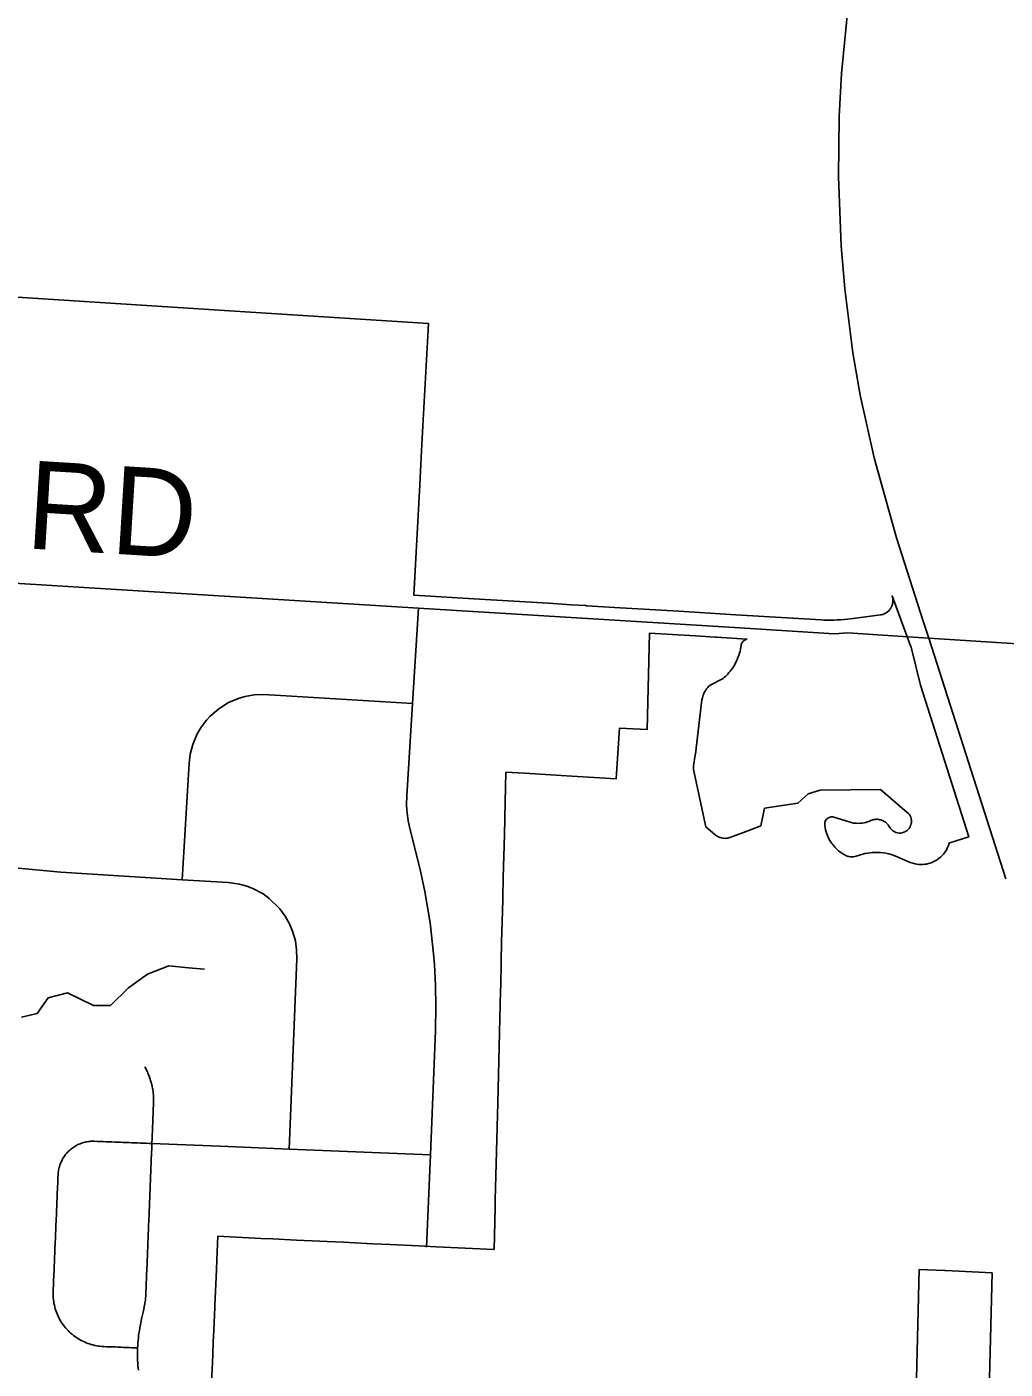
# Model space of a CAD drawing. Extents: x 114604 to 551442, y 316898 to 567001.
# Drawn here: x 175902 to 179238, y 463739 to 468313 of the extents above; entities that cross this region are included whole.
import ezdxf

# ---------------------------------------------------------------- set-up
doc = ezdxf.new("R2010")
doc.units = 0
for name, color, linetype in [('GE_P_Alignment_1000_Cardinal_Points', 7, 'Continuous'), ('GE_P_Alignment_100_Stations', 7, 'Continuous'), ('GE_P_Alignment_500_Bearings', 7, 'Continuous'), ('PM_P_Cells', 7, 'Continuous'), ('PM_P_Crosswalk', 7, 'Continuous')]:
    doc.layers.add(name, color=color, linetype=linetype)

msp = doc.modelspace()

# ---------------------------------------------------------------- linework, layer by layer
at = {"layer": 'GE_P_Alignment_1000_Cardinal_Points'}
for points in [[(173646.4, 466554.1), (173989.4, 466534.2), (174897, 466477.2), (175876.9, 466416.2), (177237.4, 466331.4), (178315.2, 466265.7), (178655.4, 466244.4), (178701.9, 466247.6), (178871.6, 466236.5)], [(177237.4, 466331.4), (177217.2, 466006.9), (177197.7, 465692.9), (177197.2, 465662.4), (177198.1, 465644.1), (177200, 465625.9), (177202.9, 465607.8), (177207.4, 465586.6), (177244.6, 465436.1), (177259.5, 465366.1), (177277.2, 465260.2), (177289.3, 465153.6), (177292.2, 465117.9), (177295.9, 465046.5), (177297.1, 464975), (177295.5, 464891.9), (177278.3, 464469.1), (177265.5, 464154.2)], [(178871.6, 466236.5), (178977.7, 466229.5), (179884.8, 466171.3), (180261.7, 466147.3)], [(176431.4, 465406.3), (176455.5, 465803.4), (176459.3, 465834), (176468.1, 465867.8), (176483.4, 465903.9), (176496.7, 465926.4), (176515.1, 465950.8), (176526.9, 465963.6), (176556.6, 465989.3), (176589.8, 466010.1), (176625.9, 466025.4), (176646.9, 466031.4), (176677, 466036.6), (176707.5, 466038.2), (176767.7, 466034.6), (177217.2, 466006.9)], [(175872.6, 465446.1), (176017.8, 465432.1), (176431.4, 465406.3), (176588.2, 465396.8), (176627.3, 465391.3), (176652.5, 465384.3), (176672.8, 465376.4), (176707.5, 465358), (176728.7, 465342.8), (176765.3, 465307), (176783.3, 465282.4), (176798.2, 465255.7), (176808.3, 465231.6), (176817.8, 465198), (176822.1, 465167.8), (176822.8, 465137.1), (176796.4, 464488.7)], [(176282.7, 463734.9), (176281.8, 463743.4), (176281.1, 463751.8), (176280.5, 463760.2), (176280, 463768.7), (176279.7, 463777.2), (176279.6, 463785.7), (176279.5, 463794.1), (176279.7, 463802.6), (176280, 463811.1), (176280.3, 463819.6), (176280.9, 463828), (176281.6, 463836.5), (176282.5, 463844.9), (176283.5, 463853.4), (176284.6, 463861.8), (176285.9, 463870.2), (176287.3, 463878.6), (176288.9, 463886.9), (176290.5, 463895.3), (176292.6, 463904.8), (176294.6, 463914.3), (176296.7, 463923.8), (176298.7, 463933.4), (176300.7, 463942.9), (176302.8, 463952.4), (176303.6, 463956.6), (176304.4, 463960.8), (176305.1, 463965), (176305.7, 463969.2), (176306.3, 463973.4), (176306.8, 463977.6), (176307.2, 463981.8), (176307.6, 463986.1), (176307.8, 463990.3), (176308.1, 463994.5), (176308.4, 464004.4), (176308.8, 464014.3), (176309.2, 464024.1), (176309.6, 464034), (176310, 464043.9), (176310.4, 464053.7), (176310.8, 464063.6), (176311.2, 464073.5), (176311.6, 464083.3), (176312, 464093.2), (176312.4, 464103.1), (176312.8, 464112.9), (176313.2, 464122.8), (176313.6, 464132.7), (176314, 464142.5), (176314.4, 464152.4), (176314.8, 464162.3), (176315.2, 464172.2), (176315.6, 464182), (176316, 464191.9), (176316.4, 464201.7), (176316.8, 464211.6), (176317.2, 464221.5), (176317.6, 464231.3), (176318, 464241.2), (176318.4, 464251.1), (176318.8, 464260.9), (176319.2, 464270.8), (176319.6, 464280.7), (176320, 464290.5), (176320.4, 464300.4), (176320.8, 464310.3), (176321.2, 464320.1), (176321.6, 464330), (176322, 464339.9), (176322.4, 464349.7), (176322.8, 464359.6), (176323.1, 464369.5), (176323.6, 464379.3), (176323.9, 464389.2), (176324.3, 464399.1), (176324.8, 464408.9), (176325.1, 464418.8), (176325.5, 464428.7), (176326, 464438.5), (176326.3, 464448.4), (176326.7, 464458.3), (176327.1, 464468.1), (176327.5, 464478), (176327.9, 464487.9), (176328.3, 464497.7), (176328.7, 464507.6), (176329.5, 464527.5), (176329.9, 464537.5), (176330.3, 464547.4), (176330.7, 464557.4), (176331.1, 464567.3), (176331.5, 464577.3), (176331.9, 464587.2), (176332.3, 464597.2), (176332.7, 464607.1), (176333.1, 464617.1), (176333.5, 464627), (176333.9, 464637), (176334.3, 464646.9), (176334.5, 464650.8), (176334.5, 464654.6), (176334.5, 464658.5), (176334.4, 464662.3), (176334.3, 464666.1), (176334.1, 464670), (176333.8, 464673.8), (176333.5, 464677.6), (176333.1, 464681.5), (176332.6, 464685.3), (176332.1, 464689.1), (176331.5, 464692.9), (176330.8, 464696.7), (176330.1, 464700.4), (176329.3, 464704.2), (176328.4, 464708), (176327.5, 464711.7), (176326.6, 464715.4), (176325.5, 464719.1), (176324.4, 464722.8), (176323.2, 464726.4), (176322, 464730.1), (176320.7, 464733.7), (176319.3, 464737.3), (176317.9, 464740.9), (176316.4, 464744.4), (176314.9, 464747.9), (176313.3, 464751.4), (176311.6, 464754.9), (176309.9, 464758.3), (176308.1, 464761.7), (176306.3, 464765.1), (176304.4, 464768.5)], [(176280, 463811.1), (176270.3, 463811.5), (176260.7, 463811.9), (176251.1, 463812.3), (176241.5, 463812.7), (176231.8, 463813.1), (176222.2, 463813.5), (176212.6, 463813.9), (176203, 463814.3), (176193.4, 463814.7), (176183.8, 463815.1), (176174.1, 463815.4), (176164.5, 463815.9), (176158.3, 463816.2), (176152.1, 463816.8), (176145.9, 463817.6), (176139.8, 463818.6), (176133.7, 463819.8), (176127.6, 463821.2), (176121.7, 463822.8), (176115.7, 463824.7), (176109.9, 463826.7), (176104, 463829), (176098.3, 463831.4), (176092.7, 463834), (176087.1, 463836.9), (176081.7, 463839.9), (176076.4, 463843.1), (176071.2, 463846.5), (176066.1, 463850), (176061.1, 463853.8), (176056.3, 463857.7), (176051.6, 463861.8), (176047, 463866), (176042.6, 463870.4), (176038.3, 463874.9), (176034.3, 463879.6), (176030.3, 463884.4), (176026.6, 463889.4), (176023, 463894.5), (176019.6, 463899.7), (176016.3, 463905), (176013.3, 463910.4), (176010.5, 463915.9), (176007.8, 463921.6), (176005.4, 463927.3), (176003.1, 463933), (176001, 463938.9), (175999.2, 463944.9), (175997.5, 463950.9), (175996, 463956.9), (175994.8, 463963), (175993.8, 463969.1), (175993, 463975.3), (175992.4, 463981.5), (175992, 463987.7), (175991.8, 463993.9), (175991.9, 464000.1), (175992.4, 464013.2), (175992.8, 464023.1), (175993.2, 464033), (175993.7, 464043), (175994, 464052.9), (175994.5, 464062.8), (175994.9, 464072.8), (175995.3, 464082.7), (175995.7, 464092.6), (175996.1, 464102.6), (175996.6, 464112.5), (175997, 464122.4), (175997.4, 464132.4), (175997.8, 464142.3), (175998.2, 464152.3), (175998.6, 464162.2), (175999.1, 464172.1), (175999.5, 464182.1), (175999.9, 464192), (176000.3, 464201.9), (176000.7, 464211.9), (176001.1, 464221.8), (176001.5, 464231.7), (176002, 464241.7), (176002.4, 464251.6), (176002.8, 464261.5), (176003.2, 464271.5), (176003.7, 464281.4), (176004, 464291.4), (176004.5, 464301.3), (176004.9, 464311.2), (176005.3, 464321.2), (176005.7, 464331.1), (176006.1, 464341), (176006.6, 464351), (176007, 464360.9), (176007.4, 464370.8), (176007.8, 464380.8), (176008.2, 464390.7), (176008.6, 464400.6), (176008.9, 464404.8), (176009.3, 464409), (176009.8, 464413.1), (176010.5, 464417.3), (176011.3, 464421.3), (176012.3, 464425.4), (176013.4, 464429.5), (176014.7, 464433.4), (176016, 464437.4), (176017.6, 464441.3), (176019.2, 464445.2), (176021, 464448.9), (176023, 464452.6), (176025, 464456.3), (176027.2, 464459.8), (176029.5, 464463.3), (176031.9, 464466.8), (176034.4, 464470.1), (176037.1, 464473.3), (176039.9, 464476.5), (176042.7, 464479.5), (176045.7, 464482.5), (176048.8, 464485.3), (176052, 464488), (176055.2, 464490.6), (176058.6, 464493.1), (176062.1, 464495.5), (176065.6, 464497.8), (176069.2, 464499.9), (176072.8, 464501.9), (176076.6, 464503.8), (176080.4, 464505.5), (176084.2, 464507.1), (176088.2, 464508.6), (176092.1, 464510), (176096.1, 464511.2), (176100.2, 464512.2), (176104.2, 464513.1), (176108.4, 464513.9), (176112.5, 464514.5), (176116.7, 464515), (176120.8, 464515.3), (176125, 464515.5), (176129.2, 464515.6), (176133.4, 464515.5), (176143.1, 464515.1), (176152.9, 464514.7), (176162.7, 464514.3), (176172.5, 464513.9), (176182.2, 464513.5), (176192, 464513.1), (176201.8, 464512.7), (176211.5, 464512.4), (176221.3, 464511.9), (176231.1, 464511.5), (176240.8, 464511.2), (176250.6, 464510.8), (176260.3, 464510.4), (176270.1, 464510), (176279.9, 464509.6), (176289.7, 464509.2), (176299.4, 464508.8), (176309.2, 464508.4), (176319, 464508), (176328.7, 464507.6), (176588.6, 464497.1)], [(176588.6, 464497.1), (176796.4, 464488.7), (177278.3, 464469.1)]]:
    msp.add_lwpolyline(points, dxfattribs=at)
at = {"layer": 'GE_P_Alignment_100_Stations'}
for points in [[(176530.8, 463670.6), (176534.8, 463762), (176535.9, 463788.4), (176537.8, 463831.7), (176539.5, 463870.4), (176543, 463950.3), (176543.2, 463955.5), (176548.5, 464077.7), (176549.9, 464109.9), (176553.4, 464191.4), (176700.2, 464184.4), (176741.2, 464182.5), (176821.7, 464178.6), (176901.6, 464174.8), (176926, 464173.7), (176981.5, 464171), (177061.4, 464167.2), (177081.9, 464166.2), (177141.3, 464163.4), (177237.9, 464158.8), (177297.9, 464156), (177495.3, 464146.6), (177498.9, 464288.4), (177499.5, 464315.8), (177501.6, 464398.1), (177507.9, 464646), (177514, 464886.4), (177517.6, 465029.2), (177518, 465045.7), (177519.9, 465123), (177520.1, 465128.9), (177521.2, 465193.5), (177523, 465263.2), (177524.8, 465338.2), (177525.1, 465347.3), (177526.7, 465413.2), (177528.6, 465488.2), (177529.4, 465520.6), (177531.6, 465609.8), (177531.8, 465617), (177533.1, 465670.5), (177535.6, 465773), (177599.4, 465769.1), (177760.9, 465759.4), (177836.7, 465754.8), (177911.9, 465750.5), (177923.2, 465923.5), (178017.4, 465918.3), (178025.4, 466247.2), (178182.3, 466237.6), (178249.8, 466233.3), (178254.1, 466233), (178357.5, 466226.7), (178357.4, 466225.8), (178356.1, 466225.5), (178353.6, 466224.7), (178351.2, 466223.7), (178349, 466222.4), (178346.8, 466220.8), (178344.9, 466219.1), (178343.1, 466217.2), (178341.6, 466215.1), (178340.3, 466212.8), (178339.2, 466210.4), (178338.1, 466206.7), (178336.4, 466196.3), (178336, 466194.4), (178335.1, 466190.2), (178334, 466185.3), (178332, 466178.7), (178331.1, 466175), (178330.1, 466172), (178328, 466166.1), (178325.8, 466160.2), (178321.9, 466151.6), (178319.1, 466146), (178316.2, 466140.5), (178311.3, 466132.4), (178306.1, 466124.5), (178300.4, 466117), (178296.4, 466112.2), (178292.3, 466107.4), (178285.7, 466100.7), (178281.2, 466096.3), (178276.5, 466092.1), (178232, 466069.8), (178227.8, 466065.9), (178223.8, 466061.8), (178220.2, 466057.3), (178216.9, 466052.7), (178215.2, 466050), (178213.6, 466047.3), (178212.1, 466044.5), (178210.8, 466041.6), (178210.2, 466040.4), (178208, 466034.9), (178206.7, 466030.8), (178205.6, 466026.7), (178204.3, 466019.6), (178185, 465854.5), (178183.3, 465842.9), (178181.5, 465831.4), (178175.3, 465795.1), (178175.1, 465782.3), (178218, 465586.6), (178232.6, 465574.2), (178249.8, 465559.5), (178253.9, 465556.4), (178256.9, 465554.5), (178259.9, 465552.8), (178263.1, 465551.4), (178266.4, 465550.2), (178269.7, 465549.2), (178274.9, 465548.2), (178278.3, 465547.8), (178283.6, 465547.6), (178287.1, 465547.9), (178292.2, 465548.6), (178295.6, 465549.5), (178299.8, 465550.8), (178345.5, 465568), (178404.6, 465590.2), (178417.9, 465650.3), (178531.6, 465667), (178566.9, 465699.6), (178607.2, 465711.9), (178813.2, 465713.9), (178904.5, 465636.1), (178908, 465632.7), (178911.5, 465628.4), (178913, 465626), (178914.9, 465622.3), (178916, 465619.7), (178917.3, 465615.7), (178918.1, 465611.6), (178918.4, 465608.9), (178918.6, 465606.1), (178918.4, 465601.9), (178917.8, 465597.7), (178916.7, 465593.7), (178915.8, 465591), (178914.1, 465587.2), (178912, 465583.6), (178910.3, 465581.3), (178907.6, 465578.2), (178905.7, 465576.2), (178902.4, 465573.5), (178897.7, 465570.5), (178892.7, 465568.2), (178887.3, 465566.6), (178881.8, 465565.7), (178876.2, 465565.7), (178870.7, 465566.4), (178865.3, 465567.9), (178861.4, 465569.5), (178857.7, 465571.5), (178854.3, 465573.8), (178851.1, 465576.5), (178848.2, 465579.6), (178846.5, 465581.7), (178844.9, 465584), (178841.7, 465589.4), (178838.6, 465593.7), (178835.1, 465597.6), (178832.6, 465600), (178829.9, 465602.2), (178825.6, 465605.2), (178822.6, 465606.9), (178819.4, 465608.4), (178814.5, 465610.2), (178811.1, 465611.1), (178807.7, 465611.8), (178802.5, 465612.4), (178799, 465612.5), (178795.5, 465612.3), (178790.3, 465611.6), (178786.9, 465610.9), (178783.6, 465609.9), (178780.3, 465608.6), (178772.8, 465605.4), (178767.9, 465603.6), (178762.8, 465602.1), (178757.8, 465600.9), (178750.9, 465599.7), (178744, 465598.9), (178737, 465598.6), (178731.7, 465598.8), (178726.5, 465599.2), (178721.3, 465599.8), (178712.8, 465601.5), (178706.1, 465603.4), (178654.1, 465620.1), (178650.2, 465620.8), (178647.6, 465620.9), (178645, 465620.8), (178641.2, 465620), (178637.5, 465618.7), (178634, 465616.8), (178630.9, 465614.4), (178628.2, 465611.6), (178626, 465608.3), (178624.3, 465604.8), (178623.5, 465602.3), (178623, 465599.7), (178622.7, 465595.8), (178622.9, 465593), (178624.3, 465583.7), (178625.8, 465576.8), (178627.6, 465570), (178629.8, 465563.3), (178632.4, 465556.7), (178634.4, 465552.1), (178637.4, 465546), (178640.8, 465539.8), (178644.6, 465533.9), (178647.3, 465530), (178650.1, 465526.2), (178654.5, 465520.7), (178657.7, 465517.2), (178662.6, 465512.1), (178666, 465508.9), (178671.4, 465504.3), (178677, 465499.9), (178682.8, 465495.9), (178688.8, 465492.2), (178692.7, 465489.9), (178697.5, 465487.8), (178702.5, 465486.2), (178705.9, 465485.4), (178711.1, 465484.6), (178716.3, 465484.4), (178721.5, 465484.8), (178725, 465485.3), (178730, 465486.6), (178744.3, 465491.5), (178753.3, 465494.1), (178759.4, 465495.6), (178768.7, 465497.4), (178778, 465498.7), (178784.3, 465499.3), (178790.5, 465499.6), (178796.8, 465499.8), (178803.1, 465499.7), (178812.5, 465499.2), (178821.9, 465498.2), (178831.2, 465496.7), (178840.4, 465494.8), (178846.5, 465493.2), (178852.5, 465491.4), (178858.5, 465489.4), (178867.3, 465486), (178914.6, 465465.5), (178922.9, 465462.6), (178931.3, 465460.5), (178936.5, 465459.6), (178943.4, 465458.8), (178950.4, 465458.5), (178957.4, 465458.6), (178964.3, 465459.3), (178969.5, 465460.1), (178976.3, 465461.6), (178982.1, 465463.3), (178987.9, 465465.4), (178992.7, 465467.4), (178997.5, 465469.7), (179003.5, 465473.1), (179007.9, 465476), (179013.5, 465480.1), (179017.6, 465483.5), (179022.6, 465488.3), (179027.3, 465493.4), (179030.6, 465497.5), (179033.7, 465501.7), (179037.5, 465507.6), (179040.8, 465513.7), (179043, 465518.5), (179045, 465523.3), (179047.7, 465531.7), (179049.1, 465532.1), (179113.8, 465552.7), (178949.6, 466070.1), (178917.1, 466198.5), (178915.3, 466203.6), (178904, 466234.1), (178853.3, 466373.4), (178855.2, 466364.3), (178855.6, 466359.8), (178855.5, 466355.8), (178855.1, 466351.4), (178854.4, 466347.4), (178853.4, 466343.6), (178852.1, 466339.8), (178850, 466335.2), (178848.5, 466332.6), (178846.1, 466328.9), (178842.9, 466325), (178839.8, 466321.7), (178836.8, 466319.1), (178832.7, 466316.2), (178827.9, 466313.5), (178825.2, 466312.2), (178820.5, 466310.5), (178816.2, 466309.4), (178813.2, 466308.8), (178719.5, 466296.3), (178700.1, 466294.1), (178688.7, 466293.1), (178677.2, 466292.3), (178665.7, 466291.7), (178654.2, 466291.3), (178642.2, 466291.1), (178630.7, 466291.2), (178619.7, 466291.5), (178611.2, 466291.7), (178319.2, 466309.5), (178231.4, 466314.9), (178125.6, 466321.3), (177925.2, 466333.4), (177811.7, 466340.3), (177810.1, 466340.4), (177810.1, 466340.4), (177809.9, 466340.4), (177809, 466340.5), (177807.8, 466340.6), (177807.1, 466340.6), (177757.7, 466343.7), (177680.5, 466348.4), (177680.4, 466348.4), (177426.5, 466364), (177221.7, 466376.5), (177221.5, 466376.6), (177241.7, 466751.7), (177245.6, 466823), (177248, 466868.3), (177252.6, 466952.9), (177257, 467034.8), (177261.4, 467116.7), (177265.8, 467198.6), (177270.2, 467280.5), (177271.4, 467302.1), (176611.8, 467344.2), (175444.7, 467418.7)], [(179172.7, 463213.4), (179193.7, 464066.7), (179034.2, 464074.5), (179031.6, 464074.6), (178945.2, 464078.9), (178911.2, 462684)]]:
    msp.add_lwpolyline(points, dxfattribs=at)
at = {"layer": 'GE_P_Alignment_500_Bearings'}
msp.add_lwpolyline([(179240.6, 465409.2), (178977.7, 466229.5), (178958.3, 466287.8), (178867.8, 466571.9), (178791.1, 466843.7), (178744.2, 467057.9), (178719.2, 467202), (178691.2, 467419.7), (178678.8, 467566.4), (178669.7, 467801.5), (178672.5, 468006.8), (178680.5, 468153.3), (178702.2, 468372.6)], dxfattribs=at)
at = {"layer": 'PM_P_Cells'}
msp.add_lwpolyline([(175883.6, 464937.9), (175937.5, 464950.2), (175975, 465004.5), (176040.8, 465021), (176129.1, 464977.6), (176187.1, 464977.9), (176248.5, 465038.4), (176314.1, 465084.9), (176385.9, 465113.4), (176453.9, 465105.9), (176507.8, 465102.2)], dxfattribs=at)

# ---------------------------------------------------------------- texts
at = {"layer": 'PM_P_Crosswalk'}
msp.add_text('RD', height=300, rotation=356.468, dxfattribs=at).set_placement((175894.7, 466536.1))

doc.saveas('drawing.dxf')
